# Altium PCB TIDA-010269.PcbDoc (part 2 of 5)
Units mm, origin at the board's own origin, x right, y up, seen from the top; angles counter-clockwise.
Board outline 87.61 x 53.51 mm, 8 copper layers (Top Layer, GND1, Signal 1, Power 1, Power 2, Signal 2, Layer 1, Bottom Layer), stack 1.645 mm thick; 482 components, 227 nets, 1562 pads, 953 vias.
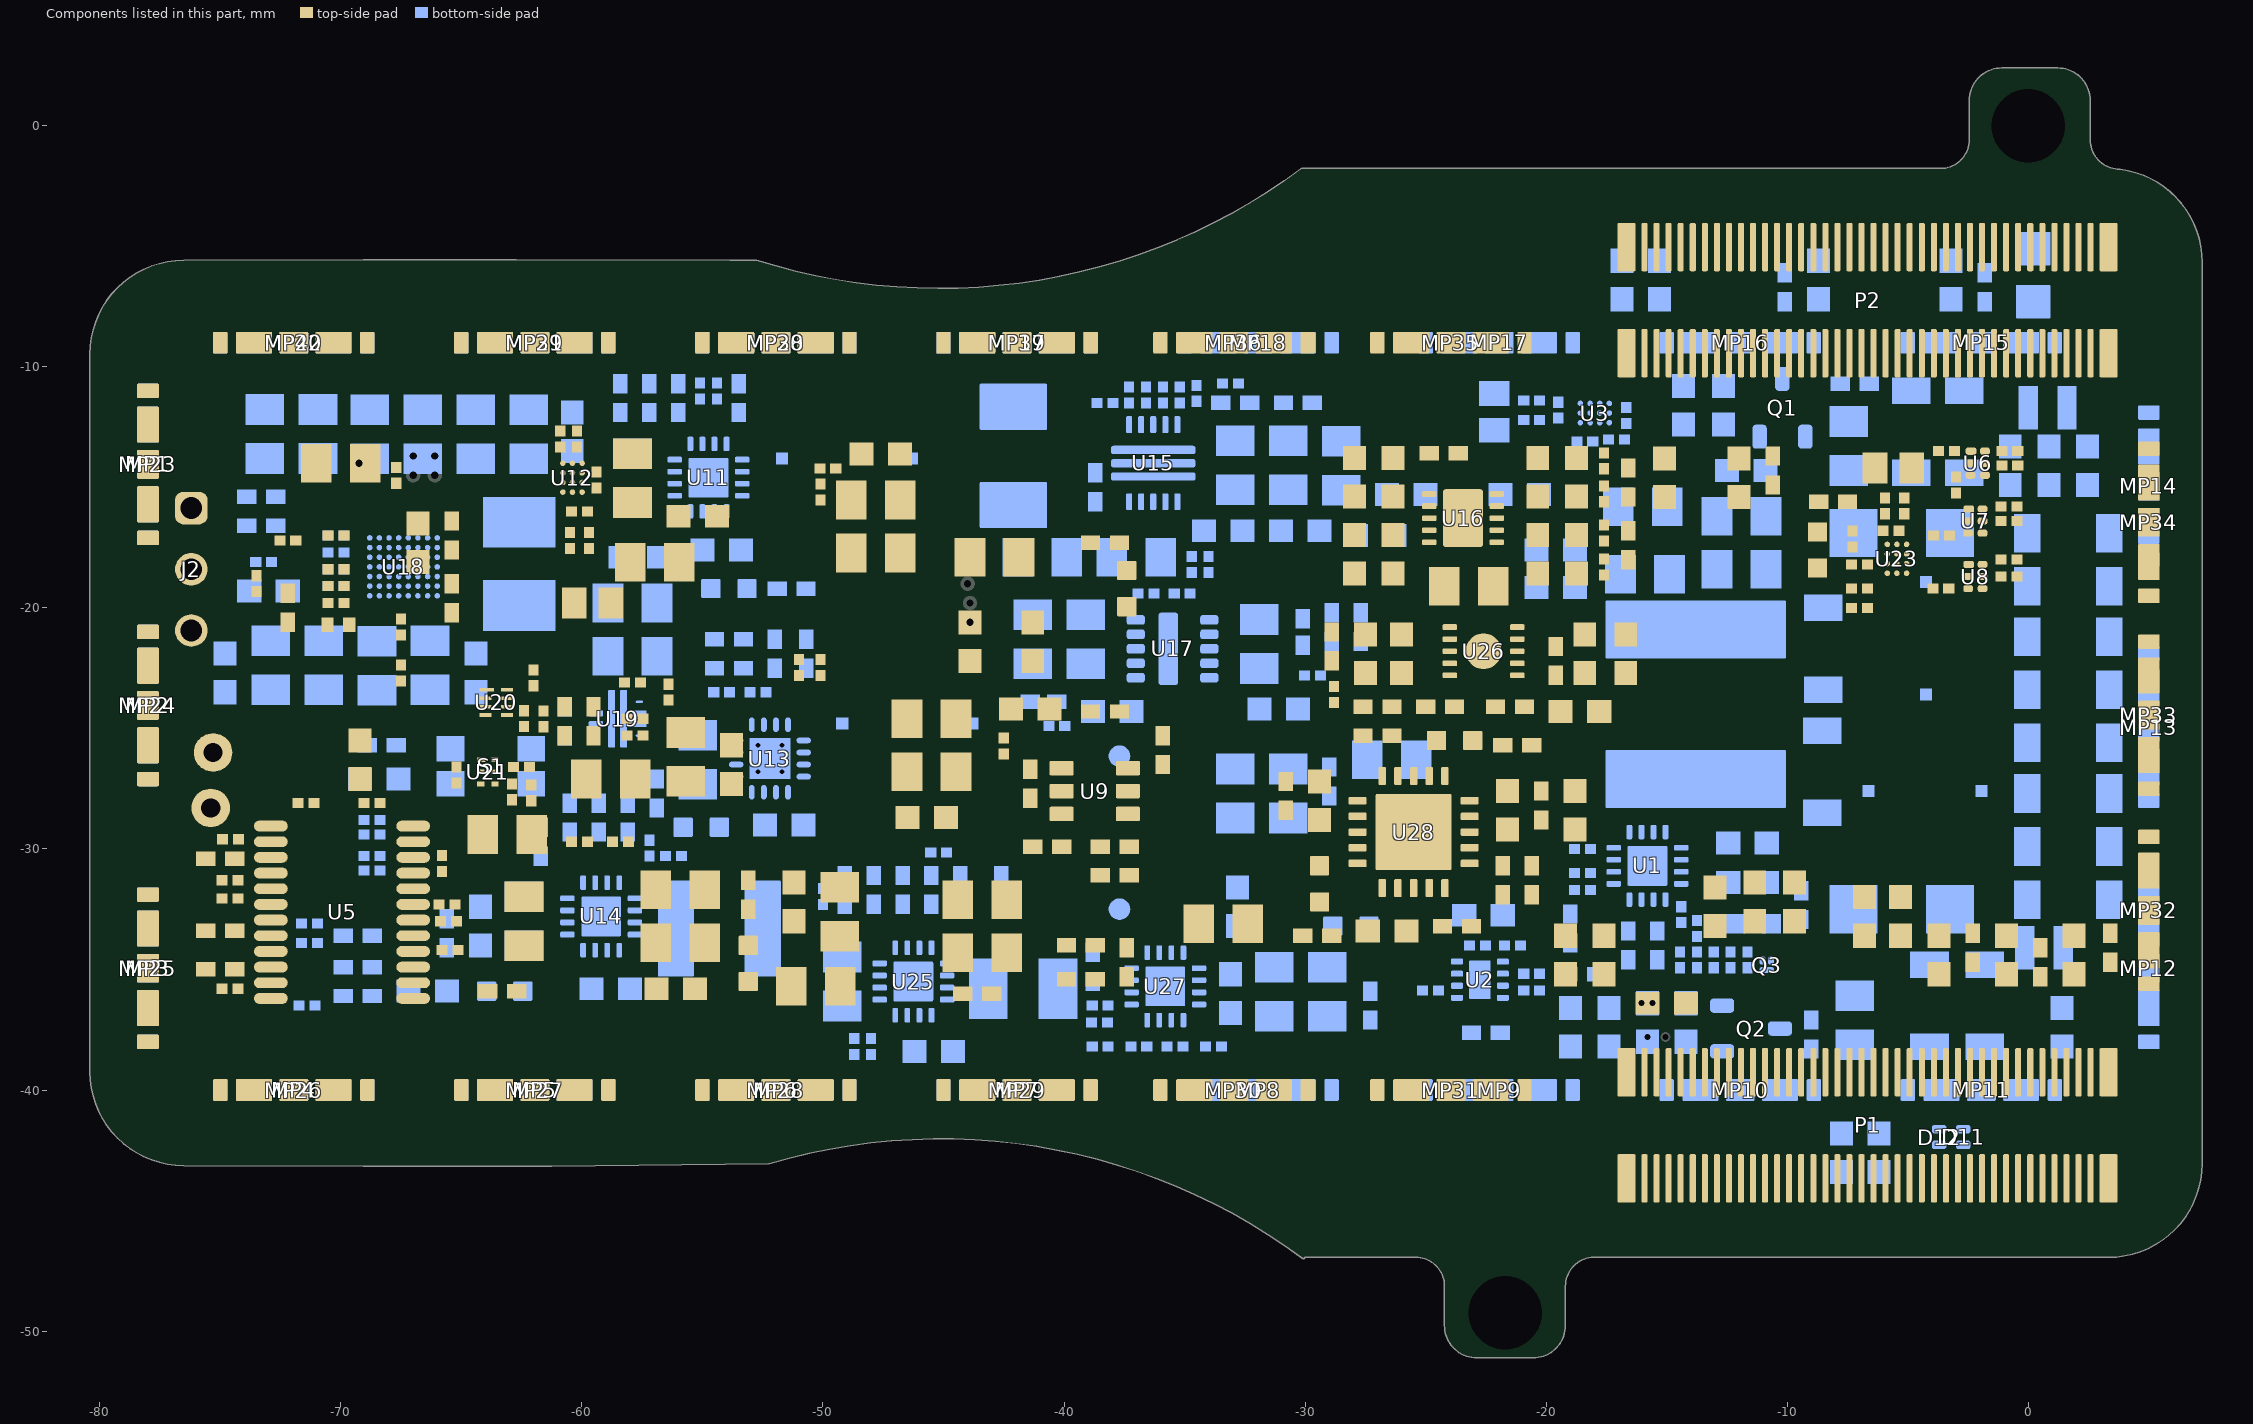
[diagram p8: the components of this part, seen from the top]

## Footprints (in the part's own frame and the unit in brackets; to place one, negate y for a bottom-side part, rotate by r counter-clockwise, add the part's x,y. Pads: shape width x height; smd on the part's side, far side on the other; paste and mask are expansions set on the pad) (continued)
DSG0008A-MFG [mm]
  rrect40% 0.5x0.25 smd paste+0 mask+0: 1(-0.95,0.75) 2(-0.95,0.25) 3(-0.95,-0.25) 4(-0.95,-0.75) 5(0.95,-0.75) 6(0.95,-0.25) 7(0.95,0.25) 8(0.95,0.75)
  rrect11% 0.9x1.6 smd paste-1000 mask+0: 9(0,0)
  silkscreen extent -1.88,-1.39 1,1.4, body extent -1,-1 1,1, height 0.8
FCC_disclaimer [mm]
FP-HCJ0805ZT0R00_0805-MFG [mm]
  rrect7% 1.4x1.44 smd paste+0 mask+0: 1(-1.1,0) 2(1.1,0)
  silkscreen extent 0,-0.72 0,0.72, body extent -1,-0.6 1,0.6, height 0.85
HSMx-C190_Amber [mm] "SMD, 2-Leads, Body 1.6x0.8mm"
  rect 0.8x0.8 smd: 1(-0.75,0) 2(0.75,0)
  silkscreen extent -1.2,-0.8 1.85,0.8, body extent -0.85,-0.45 0.85,0.45, height 0.9
HSMx-C191_Red [mm] "SMD, 2-Leads, Body 1.6x0.8mm"
  rrect12% 0.8x0.8 smd: 1(-0.75,0) 2(0.75,0)
  silkscreen extent -1.2,-0.8 1.85,0.8, body extent -0.85,-0.45 0.85,0.45, height 0.7
IHLP-2020CZ [mil] "Vishay Dale"
  rrect5% 75.5x110 smd: 1(-80.25,0) 2(80.25,0)
  silkscreen extent -101,-101 101,101, body extent -107,-101 107,101, height 113
LTST-C193_Green [mm] "SMD, 2-Leads, Body1.6x0.8mm"
  rect 0.8x0.8 smd: 1(-0.75,0) 2(0.75,0)
  silkscreen extent -1.2,-0.9 1.85,0.9, body extent -0.85,-0.45 0.85,0.45, height 0.45
Mill-Max_801-41-003-10-001000 [mm] "Receptacle, 2.54mm, 3x1, TH"
  rrect50% 1.35x1.35 hole 0.9: 1(-2.54,0)
  round 1.35 hole 0.9: 2(0,0) 3(2.54,0)
  silkscreen extent -3.81,-1.75 3.81,1.27, body extent -3.81,-1.27 3.81,1.27, height 7.01
NRS5030 [mm] "Taito Yuden"
  rrect7% 1.5x4 smd: 1(-1.8,0) 2(1.8,0)
  silkscreen extent -2.6,-2.6 2.6,2.6, body extent -2.55,-2.55 2.55,2.55, height 3.1
Panasonic_AXK5S80347Y [mm] "Receptacle, 0.5mm, 40x2, SMD"
  rrect13% 0.75x2 smd paste-2: 1(-10,2.2) 2(-10,-2.2) 79(10,2.2) 80(10,-2.2)
  rrect40% 0.25x2 smd paste-2: 3(-9.25,2.2) 4(-9.25,-2.2) 5(-8.75,2.2) 6(-8.75,-2.2) 7(-8.25,2.2) 8(-8.25,-2.2) 9(-7.75,2.2) 10(-7.75,-2.2) 11(-7.25,2.2) 12(-7.25,-2.2) 13(-6.75,2.2) 14(-6.75,-2.2) 15(-6.25,2.2) 16(-6.25,-2.2) 17(-5.75,2.2) 18(-5.75,-2.2) 19(-5.25,2.2) 20(-5.25,-2.2) 21(-4.75,2.2) 22(-4.75,-2.2) 23(-4.25,2.2) 24(-4.25,-2.2) 25(-3.75,2.2) 26(-3.75,-2.2) 27(-3.25,2.2) 28(-3.25,-2.2) 29(-2.75,2.2) 30(-2.75,-2.2) 31(-2.25,2.2) 32(-2.25,-2.2) 33(-1.75,2.2) 34(-1.75,-2.2) 35(-1.25,2.2) 36(-1.25,-2.2) 37(-0.75,2.2) 38(-0.75,-2.2) 39(-0.25,2.2) 40(-0.25,-2.2) 41(0.25,2.2) 42(0.25,-2.2) 43(0.75,2.2) 44(0.75,-2.2) 45(1.25,2.2) 46(1.25,-2.2) 47(1.75,2.2) 48(1.75,-2.2) 49(2.25,2.2) 50(2.25,-2.2) 51(2.75,2.2) 52(2.75,-2.2) 53(3.25,2.2) 54(3.25,-2.2) 55(3.75,2.2) 56(3.75,-2.2) 57(4.25,2.2) 58(4.25,-2.2) 59(4.75,2.2) 60(4.75,-2.2) 61(5.25,2.2) 62(5.25,-2.2) 63(5.75,2.2) 64(5.75,-2.2) 65(6.25,2.2) 66(6.25,-2.2) 67(6.75,2.2) 68(6.75,-2.2) 69(7.25,2.2) 70(7.25,-2.2) 71(7.75,2.2) 72(7.75,-2.2) 73(8.25,2.2) 74(8.25,-2.2) 75(8.75,2.2) 76(8.75,-2.2) 77(9.25,2.2) 78(9.25,-2.2)
  body extent -11.6,-2.7 11.6,2.7, height 6.05
PREYBG0056 [mm] "BGA, 56-Balls, Body 2.955x3.455mm, Pitch 0.4mm"
  round 0.23 smd paste-0.23: A1(-1.2,1.4) A2(-0.8,1.4) A3(-0.4,1.4) A4(0,1.4) A5(0.4,1.4) A6(0.8,1.4) A7(1.2,1.4) B1(-1.2,1) B2(-0.8,1) B3(-0.4,1) B4(0,1) B5(0.4,1) B6(0.8,1) B7(1.2,1) C1(-1.2,0.6) C2(-0.8,0.6) C3(-0.4,0.6) C4(0,0.6) C5(0.4,0.6) C6(0.8,0.6) C7(1.2,0.6) D1(-1.2,0.2) D2(-0.8,0.2) D3(-0.4,0.2) D4(0,0.2) D5(0.4,0.2) D6(0.8,0.2) D7(1.2,0.2) E1(-1.2,-0.2) E2(-0.8,-0.2) E3(-0.4,-0.2) E4(0,-0.2) E5(0.4,-0.2) E6(0.8,-0.2) E7(1.2,-0.2) F1(-1.2,-0.6) F2(-0.8,-0.6) F3(-0.4,-0.6) F4(0,-0.6) F5(0.4,-0.6) F6(0.8,-0.6) F7(1.2,-0.6) G1(-1.2,-1) G2(-0.8,-1) G3(-0.4,-1) G4(0,-1) G5(0.4,-1) G6(0.8,-1) G7(1.2,-1) H1(-1.2,-1.4) H2(-0.8,-1.4) H3(-0.4,-1.4) H4(0,-1.4) H5(0.4,-1.4) H6(0.8,-1.4) H7(1.2,-1.4)
  body extent -1.49,-1.74 1.49,1.74, height 0.5
PW0024A_N [mm] "TSOP, 24-Leads, Body 7.8x4.4mm, Pitch 0.65mm, IPC Medium Density"
  oval 1.4x0.45 smd: 1(-2.95,3.575) 2(-2.95,2.925) 3(-2.95,2.275) 4(-2.95,1.625) 5(-2.95,0.975) 6(-2.95,0.325) 7(-2.95,-0.325) 8(-2.95,-0.975) 9(-2.95,-1.625) 10(-2.95,-2.275) 11(-2.95,-2.925) 12(-2.95,-3.575) 13(2.95,-3.575) 14(2.95,-2.925) 15(2.95,-2.275) 16(2.95,-1.625) 17(2.95,-0.975) 18(2.95,-0.325) 19(2.95,0.325) 20(2.95,0.975) 21(2.95,1.625) 22(2.95,2.275) 23(2.95,2.925) 24(2.95,3.575)
  silkscreen extent -3.51,-3.95 1.6,4.04, body extent -3.21,-3.9 3.21,3.9, height 1
RGW0020A [mm] "VQFN-20"
  rrect32% 0.75x0.31 smd: 1(-2.325,1.3) 2(-2.325,0.65) 3(-2.325,0) 4(-2.325,-0.65) 5(-2.325,-1.3) 11(2.325,-1.3) 12(2.325,-0.65) 13(2.325,0) 14(2.325,0.65) 15(2.325,1.3)
  rrect32% 0.31x0.75 smd: 6(-1.3,-2.325) 7(-0.65,-2.325) 8(0,-2.325) 9(0.65,-2.325) 10(1.3,-2.325) 16(1.3,2.325) 17(0.65,2.325) 18(0,2.325) 19(-0.65,2.325) 20(-1.3,2.325)
  rrect3% 3.15x3.15 smd paste-1.575: 21(0,0)
  body extent -2.5,-2.5 2.5,2.5, height 1
RNW0013A [mm] "SMD, 13-Leads, Body 3x3.5mm, Pitch 0.5mm"
  rrect40% 0.7x0.25 smd: 1(-1.6,1) 2(-1.6,0.5) 3(-1.6,0) 4(-1.6,-0.5) 5(-1.6,-1) 9(1.6,-1) 10(1.6,-0.5) 11(1.6,0) 12(1.6,0.5) 13(1.6,1)
  rrect40% 0.25x1 on Bottom Paste: 6(-0.55,-1.2) 6(-0.55,0) 6(-0.55,1.2) 7(0,-1.2) 7(0,0) 7(0,1.2) 8(0.55,-1.2) 8(0.55,0) 8(0.55,1.2)
  rrect57% 0.35x3.5 smd paste-0.5 mask-0.05: 6(-0.55,0) 7(0,0) 8(0.55,0)
  silkscreen extent -1.9,-1.65 1.9,1.65, body extent -1.78,-1.53 1.78,1.53, height 1.01
RPW0010A [mm] "VQFN-HR-10"
  rrect100% 0.3x0.1 smd: 1(-0.9,0.7) 4(-0.9,-0.7) 7(0.9,-0.7) 10(0.9,0.7)
  rrect40% 0.6x0.25 smd: 2(-0.9,0.225) 3(-0.9,-0.225) 8(0.9,-0.225) 9(0.9,0.225)
  rrect33% 0.3x2.4 smd paste-0.25: 5(-0.25,0) 6(0.25,0)
  Top Layer region: -0.65,-0.55 -0.631,-0.554 -0.615,-0.565 -0.604,-0.581 -0.6,-0.6 -0.6,-0.6 -0.6,-1.15 -0.604,-1.169 -0.615,-1.185 -0.631,-1.196 -0.65,-1.2 -0.65,-1.2 -0.8,-1.2 -0.819,-1.196 -0.835,-1.185 -0.846,-1.169 -0.85,-1.15 -0.85,-1.15 -0.85,-0.85 -1.15,-0.85 -1.169,-0.846 -1.185,-0.835 -1.196,-0.819 -1.2,-0.8 -1.2,-0.8 -1.2,-0.6 -1.196,-0.581 -1.185,-0.565 -1.169,-0.554 -1.15,-0.55 -1.15,-0.55
  Top Layer region: -0.65,0.55 -0.631,0.554 -0.615,0.565 -0.604,0.581 -0.6,0.6 -0.6,0.6 -0.6,1.15 -0.604,1.169 -0.615,1.185 -0.631,1.196 -0.65,1.2 -0.65,1.2 -0.8,1.2 -0.819,1.196 -0.835,1.185 -0.846,1.169 -0.85,1.15 -0.85,1.15 -0.85,0.85 -1.15,0.85 -1.169,0.846 -1.185,0.835 -1.196,0.819 -1.2,0.8 -1.2,0.8 -1.2,0.6 -1.196,0.581 -1.185,0.565 -1.169,0.554 -1.15,0.55 -1.15,0.55
  Top Layer region: 0.65,0.55 0.631,0.554 0.615,0.565 0.604,0.581 0.6,0.6 0.6,0.6 0.6,1.15 0.604,1.169 0.615,1.185 0.631,1.196 0.65,1.2 0.65,1.2 0.8,1.2 0.819,1.196 0.835,1.185 0.846,1.169 0.85,1.15 0.85,1.15 0.85,0.85 1.15,0.85 1.169,0.846 1.185,0.835 1.196,0.819 1.2,0.8 1.2,0.8 1.2,0.6 1.196,0.581 1.185,0.565 1.169,0.554 1.15,0.55 1.15,0.55
  Top Layer region: 0.65,-0.55 0.631,-0.554 0.615,-0.565 0.604,-0.581 0.6,-0.6 0.6,-0.6 0.6,-1.15 0.604,-1.169 0.615,-1.185 0.631,-1.196 0.65,-1.2 0.65,-1.2 0.8,-1.2 0.819,-1.196 0.835,-1.185 0.846,-1.169 0.85,-1.15 0.85,-1.15 0.85,-0.85 1.15,-0.85 1.169,-0.846 1.185,-0.835 1.196,-0.819 1.2,-0.8 1.2,-0.8 1.2,-0.6 1.196,-0.581 1.185,-0.565 1.169,-0.554 1.15,-0.55 1.15,-0.55
  body extent -1,-1 1,1, height 1.01
RTE0016F#1 [mm] "Texas Insturments"
  rrect42% 0.6x0.24 smd: 1(-1.4,0.75) 2(-1.4,0.25) 3(-1.4,-0.25) 4(-1.4,-0.75) 9(1.4,-0.75) 10(1.4,-0.25) 11(1.4,0.25) 12(1.4,0.75)
  rrect42% 0.24x0.6 smd: 5(-0.75,-1.4) 6(-0.25,-1.4) 7(0.25,-1.4) 8(0.75,-1.4) 13(0.75,1.4) 14(0.25,1.4) 15(-0.25,1.4) 16(-0.75,1.4)
  rrect6% 1.65x1.65 smd paste-0.85: 17(0,0)
  rrect7% 1.51x1.51 on Bottom Paste: 17(0,0)
  silkscreen extent -1.73,-1.72 1.72,1.72, body extent -1.5,-1.5 1.5,1.5, height 0.8
RTE0016F#2 [mm] "Texas Insturments"
  oval 0.6x0.24 smd paste+0: 1(-1.4,0.75) 2(-1.4,0.25) 3(-1.4,-0.25) 4(-1.4,-0.75) 9(1.4,-0.75) 10(1.4,-0.25) 11(1.4,0.25) 12(1.4,0.75)
  oval 0.24x0.6 smd paste+0: 5(-0.75,-1.4) 6(-0.25,-1.4) 7(0.25,-1.4) 8(0.75,-1.4) 13(0.75,1.4) 14(0.25,1.4) 15(-0.25,1.4) 16(-0.75,1.4)
  rect 1.7x1.7 smd paste-1: 17(0,0)
  silkscreen extent -1.72,-1.73 1.72,1.73, body extent -1.58,-1.58 1.58,1.58, height 0.81
RTE0016K-MFG [mm]
  rrect42% 0.6x0.24 smd paste+0 mask+0: 1(-1.4,0.75) 2(-1.4,0.25) 3(-1.4,-0.25) 4(-1.4,-0.75) 9(1.4,-0.75) 10(1.4,-0.25) 11(1.4,0.25) 12(1.4,0.75)
  rrect42% 0.24x0.6 smd paste+0 mask+0: 5(-0.75,-1.4) 6(-0.25,-1.4) 7(0.25,-1.4) 8(0.75,-1.4) 13(0.75,1.4) 14(0.25,1.4) 15(-0.25,1.4) 16(-0.75,1.4)
  rrect6% 1.66x1.66 smd paste-1000 mask+0: 17(0,0)
  silkscreen extent -2.4,-1.58 1.58,1.57, body extent -1.5,-1.5 1.5,1.5, height 0.8
SIL0010A [mm] "MicoSiP, TI recommended land pattern"
  rrect50% 0.75x0.4 smd paste-0.05 mask-0.05: 1(-1.525,1.2) 2(-1.525,0.6) 3(-1.525,0) 4(-1.525,-0.6) 5(-1.525,-1.2) 6(1.525,-1.2) 7(1.525,-0.6) 8(1.525,0) 9(1.525,0.6) 10(1.525,1.2)
  rrect14% 0.7x0.833 on Bottom Paste: 11(-0.175,-1.03) 11(-0.175,0) 11(-0.175,1.03)
  rrect25% 0.8x3 smd paste-0.5 mask-0.05: 11(-0.175,0)
  silkscreen extent -1.9,-1.67 1.9,1.68, body extent -1.9,-1.5 1.9,1.5, height 1.49
SMA [mm] "Molded Diode, 2-Leads, Body 4.3x2.6mm, IPC Medium Density, based on OnSemi component dimensions and land pattern"
  rect 2x2 smd: 1(-2,0) 2(2,0)
  silkscreen extent -3.66,-1.57 2.79,1.58, body extent -2.6,-1.3 2.6,1.3, height 2.42
SML-P1_GREEN [mm] "ROHM"
  rect 0.5x0.6 smd: 1(-0.45,0) 2(0.45,0)
  silkscreen extent -0.95,-0.3 -0.95,0.3, body extent -0.53,-0.33 0.53,0.33, height 0.25
SOD-523 [mm] "NXP Semiconductor recommended land pattern, nominal STEP model"
  rect 0.8x0.6 smd paste-0.05: 1(-0.55,0) 2(0.55,0)
  silkscreen extent -1.65,-0.66 1.2,0.66, body extent -0.8,-0.4 0.8,0.4, height 0.72
SOT-23 [mm] "SOT23, 3-Leads, Body 2.9x1.3mm, Pitch 0.95mm, Lead Span 2.5mm, IPC Medium Density"
  rrect50% 1x0.6 smd: 1(-1.2,0.95) 2(-1.2,-0.95) 3(1.2,0)
  silkscreen extent -1.63,-1.5 0.7,1.5, body extent -1.16,-1.45 1.21,1.45, height 1
SW_434153017835 [mm] "SMD, 4-Leads, Body 3.5x2.9mm"
  rect 1.15x1.05 smd: 1(-1.675,0.725) 2(-1.675,-0.725) 3(1.675,0.725) 4(1.675,-0.725)
  silkscreen extent -0.7,-1.4 0.7,1.6, body extent -2.15,-1.45 2.15,1.45, height 1.7
TESTPOINT [mm]
  round 1.6 hole 0.8: 1(0,0)
TI_Stacked_Overlay_Small [mm]
  silkscreen extent -10.63,-2.49 10.63,2.49
VLCF4020 [mm] "TDK"
  rect 1.6x2.5 smd: 1(-1.45,0) 2(1.45,0)
  Top Layer region: 0.65,-1.95 1.55,-1.95 2.25,-1.25 2.25,-1.15 0.65,-1.15
  Top Layer region: 0.65,1.95 1.55,1.95 2.25,1.25 2.25,1.15 0.65,1.15
  Top Layer region: -0.65,1.95 -1.55,1.95 -2.25,1.25 -2.25,1.15 -0.65,1.15
  Top Layer region: -0.65,-1.95 -1.55,-1.95 -2.25,-1.25 -2.25,-1.15 -0.65,-1.15
  silkscreen extent -0.4,-2.1 0.4,2.1, body extent -2.05,-2.05 2.05,2.05, height 2
VLCF5020 [mm] "TDK"
  rect 2.1x3 smd: 1(-1.725,0) 2(1.725,0)
  Top Layer region: -0.675,2.45 -1.875,2.45 -2.775,1.55 -2.775,1.4 -0.675,1.4
  Top Layer region: -0.675,-2.45 -1.875,-2.45 -2.775,-1.55 -2.775,-1.4 -0.675,-1.4
  Top Layer region: 0.675,-2.45 1.875,-2.45 2.775,-1.55 2.775,-1.4 0.675,-1.4
  Top Layer region: 0.675,2.4 1.875,2.4 2.775,1.5 2.775,1.35 0.675,1.35
  body extent -2.6,-2.6 2.6,2.6, height 2
WE-LQS_8040 [mm] "SMD, 2-Leads, Body 8x8mm"
  rrect4% 2.4x7.5 smd: 1(-3.1,0) 2(3.1,0)
  body extent -4,-4 4,4, height 4.2
WE-PMI_0806HS [mm] "WURTH"
  rect 0.8x1.8 smd: 1(-0.8,0) 2(0.8,0)
  body extent -1.1,-0.9 1.1,0.9, height 1
WE-TPC-LH [mm] "Wurth Elektronik recommended land pattern, 2009-01-15"
  rect 0.5x0.5 smd: 1(-2.7,0) 2(2.7,0)
  Top Layer region: -0.95,3.15 -0.95,3.15 -0.95,1.987 -1.228,1.838 -1.563,1.563 -1.838,1.228 -2.042,0.846 -2.168,0.431 -2.211,0 -2.168,-0.431 -2.042,-0.846 -1.838,-1.228 -1.563,-1.563 -1.228,-1.838 -0.95,-1.987 -0.95,-3.15 -3.15,-3.15 -3.15,-3.15 -3.15,3.15 -0.95,3.15
  Top Layer region: 0.95,3.15 0.95,3.15 0.95,1.987 1.228,1.838 1.563,1.563 1.838,1.228 2.042,0.846 2.168,0.431 2.211,0 2.168,-0.431 2.042,-0.846 1.838,-1.228 1.563,-1.563 1.228,-1.838 0.95,-1.987 0.95,-3.15 3.15,-3.15 3.15,-3.15 3.15,3.15 0.95,3.15
  silkscreen extent -3.4,-3.4 3.4,3.4, body extent -3.05,-3.05 3.05,3.05, height 3
WE-TPC_4828 [mm] "Wurth Elektronik recommended land pattern"
  rect 0.5x0.5 smd: 1(-2.35,0) 2(2.325,0)
  Top Layer region: 0.75,1.64 1.005,1.504 1.279,1.279 1.504,1.005 1.671,0.692 1.774,0.353 1.809,0 1.774,-0.353 1.671,-0.692 1.504,-1.005 1.279,-1.279 1.005,-1.504 0.75,-1.64 0.75,-2.65 2.75,-2.65 2.75,2.65 0.75,2.65
  Top Layer region: -0.75,1.64 -1.005,1.504 -1.279,1.279 -1.504,1.005 -1.671,0.692 -1.774,0.353 -1.809,0 -1.774,-0.353 -1.671,-0.692 -1.504,-1.005 -1.279,-1.279 -1.005,-1.504 -0.75,-1.64 -0.75,-2.65 -2.75,-2.65 -2.75,2.65 -0.75,2.65
  silkscreen extent -0.5,-2.6 0.5,2.63, body extent -2.5,-2.5 2.5,2.5, height 2
WE-TPC_6823 [mm] "Wurth"
  round 0.9 smd: 1(0,3.2) 2(0,-3.15)
  Top Layer region: 3.65,-1.05 2.5,-1.05 2.485,-1.055 1.743,-2.062 0.626,-2.626 -0.626,-2.626 -1.743,-2.062 -2.485,-1.055 -2.485,-1.055 -2.5,-1.05 -3.65,-1.05 -3.65,-3.65 3.65,-3.65
  Top Layer region: -3.65,1.05 -2.5,1.05 -2.485,1.055 -1.743,2.062 -0.626,2.626 0.626,2.626 1.743,2.062 2.485,1.055 2.485,1.055 2.5,1.05 3.65,1.05 3.65,3.65 -3.65,3.65
  silkscreen extent -3.6,-0.8 3.6,0.8, body extent -3.5,-3.5 3.5,3.5, height 2.5
WEEE_Minimum [mm] "WEEElie bin"
  silkscreen extent -2.42,-4.38 2.52,2.65
WSLP0805 [mm] "Vishay"
  rect 1.02x1.27 smd: 1(-0.76,0) 2(0.76,0)
  silkscreen extent -0.6,-0.9 0.6,0.9, body extent -1.14,-0.76 1.14,0.76, height 0.64
YFF0012AKAD [mm] "TI DSBGA 1.675x1.418mm"
  round 0.23 smd paste-0.13 mask+0.038: A1(-0.4,0.6) A2(0,0.6) A3(0.4,0.6) B1(-0.4,0.2) B2(0,0.2) B3(0.4,0.2) C1(-0.4,-0.2) C2(0,-0.2) C3(0.4,-0.2) D1(-0.4,-0.6) D2(0,-0.6) D3(0.4,-0.6)
  silkscreen extent -0.8,-0.93 0.8,0.92, body extent -0.71,-0.84 0.71,0.84, height 0.63
YJM0003A [mm] "SMT, 3-Leads, Body 0.69x0.6mm"
  rrect80% 0.35x0.25 smd paste-0.2 mask-0.05: 1(-0.175,0.175) 2(-0.175,-0.175)
  rrect50% 0.25x0.2 on Bottom Paste: 1(-0.175,0.2) 2(-0.175,-0.2)
  rrect80% 0.25x0.6 smd paste-0.05 mask-0.05: 3(0.225,0)
  body extent -0.35,-0.3 0.35,0.3, height 0.35

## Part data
C1 C6 C7 C8 C9 C10 C11 C15 C18 C19 C20 C21 C22 C23: library part CMP-0008724-2, "CAP, CERM, 2.2 uF, 100 V, +/- 10%, X7S, 1206", Cap_Case=1206_180, Manufacturer=TDK, Supplier Part Number 1=445-5207-1-ND, TempCo=X7S, Tolerance_%=10%, Value1="0.005718 ohm", Value2=100V, ValueDisplayed=2.2uF
C2: library part CMP-0007891-2, "CAP, CERM, 1 uF, 100 V, +/- 10%, X7S, 0805", Cap_Case=0805, Manufacturer=TDK, Supplier Part Number 1=445-5205-1-ND, TempCo=X7S, Tolerance_%=10%, Value1="0.008255 ohm", Value2=100V, ValueDisplayed=1uF
C3 C4 C58 C59 C63 C64 C72 C74 C75 C76 C79 C81 C82 C84 C95 C96 C99 C100 C101 C123 C131 C132 C139 C140 C141 C174 C175 C177 C178 C192 C193 C195 C196: library part CMP-0078699-1, "CAP, CERM, 47 µF, 10 V,+/- 20%, X5R, 0805", Cap_Case=0805, Manufacturer=MuRata, Supplier Part Number 1=490-9961-1-ND, TempCo=X5R, Tolerance_%=20%, Value2=10V, ValueDisplayed=47µF
C5 C25 C56 C57 C60 C65 C70 C71 C73 C77 C83 C85 C107 C109 C114 C117 C122 C125 C130 C133 C143 C150 C154 C155 C171 C176 C183 C189 C194: library part CMP-0006837-2, "CAP, CERM, 0.1 uF, 50 V, +/- 10%, X7R, 0603", Cap_Case=0603, Manufacturer="Wurth Elektronik", TempCo=X7R, Tolerance_%=10%, Value1=Unknown, Value2=50V, ValueDisplayed=0.1uF
C12: library part CMP-0007297-3, "CAP, CERM, 4.7 uF, 25 V, +/- 10%, X6S, 0603", Cap_Case=0603, Manufacturer=MuRata, Supplier Part Number 1=490-7199-1-ND, TempCo=X6S, Tolerance_%=10%, Value1=Unknown, Value2=25V, ValueDisplayed=4.7uF
C13 C17: library part CMP-0007470-5, "CAP, CERM, 0.1 uF, 100 V, +/- 10%, X7R, 0603", Cap_Case=0603, Manufacturer=MuRata, Supplier Part Number 1=490-6439-1-ND, TempCo=X7R, Tolerance_%=10%, Value1=Unknown, Value2=100V, ValueDisplayed=0.1uF
C14: library part CMP-0079154-1, "CAP, CERM, 1 µF, 16 V,+/- 10%, X7R, AEC-Q200 Grade 1, 0603", Cap_Case=0603, Manufacturer=MuRata, Supplier Part Number 1=490-12657-1-ND, TempCo=X7R, Tolerance_%=10%, Value2=16V, ValueDisplayed=1µF
C16 C24 C29 C39 C40 C43 C51 C52 C68 C91 C92 C94 C108 C137 C152 C153 C179 C180 C187 C191 C197 C200 C202 C205 C207: library part CMP-0006607-1, "CAP, CERM, 0.1 uF, 25 V, +/- 10%, X5R, 0402", Cap_Case=0402, Manufacturer=MuRata, Supplier Part Number 1=490-5920-1-ND, TempCo=X5R, Tolerance_%=10%, Value1=Unknown, Value2=25V, ValueDisplayed=0.1uF
C26 C27 C32 C34 C35 C53 C54 C55 C61 C66 C135 C138 C148 C151 C157: library part CMP-0009637-1, "CAP, CERM, 0.1 uF, 16 V, +/- 10%, X6S, 0201", Cap_Case=0201, Manufacturer=TDK, Supplier Part Number 1=445-15903-1-ND, TempCo=X6S, Tolerance_%=10%, Value1=Unknown, Value2=16V, ValueDisplayed=0.1uF
C28: library part CMP-0006663-2, "CAP, CERM, 2200 pF, 25 V, +/- 10%, X7R, 0402", Cap_Case=0402, Manufacturer=MuRata, Supplier Part Number 1=490-5419-1-ND, TempCo=X7R, Tolerance_%=10%, Value1=Unknown, Value2=25V, ValueDisplayed=2200pF
C30 C104: library part CMP-0009762-1, "CAP, CERM, 100 pF, 25 V, +/- 5%, C0G/NP0, 0201", Cap_Case=0201, Manufacturer=MuRata, Supplier Part Number 1=81-GRM033R71E101JA1D, TempCo=C0G/NP0, Tolerance_%=5%, Value1=Unknown, Value2=25V, ValueDisplayed=100pF
C31: library part CMP-0007891-1, "CAP, CERM, 1 uF, 100 V, +/- 10%, X7S, 0805", Cap_Case=0805, Manufacturer=TDK, Supplier Part Number 1=445-5205-1-ND, TempCo=X7S, Tolerance_%=10%, Value1="0.008255 ohm", Value2=100V, ValueDisplayed=1uF
C33: library part CMP-0006563-2, "CAP, CERM, 1 uF, 10 V, +/- 10%, X5R, 0402", Cap_Case=0402, Manufacturer=MuRata, Supplier Part Number 1=490-3890-1-ND, TempCo=X5R, Tolerance_%=10%, Value1=Unknown, Value2=10V, ValueDisplayed=1uF
C41 C42: library part CMP-0006607-2, "CAP, CERM, 0.1 uF, 25 V, +/- 10%, X5R, 0402", Cap_Case=0402, Manufacturer=MuRata, Supplier Part Number 1=490-5920-1-ND, TempCo=X5R, Tolerance_%=10%, Value1=Unknown, Value2=25V, ValueDisplayed=0.1uF
C47 C97 C169 C184: library part CMP-0007329-4, "CAP, CERM, 4.7 uF, 10 V, +/- 20%, X5R, 0603", Cap_Case=0603, Manufacturer=MuRata, TempCo=X5R, Tolerance_%=20%, Value1=Unknown, Value2=10V, ValueDisplayed=4.7uF
C50: library part CMP-0006286-1, "CAP, CERM, 1 uF, 16 V, +/- 10%, X6S, 0402", Cap_Case=0402, Manufacturer=TDK, Supplier Part Number 1=445-9086-1-ND, TempCo=X6S, Tolerance_%=10%, Value1="0.011416 ohm", Value2=16V, ValueDisplayed=1uF
C62 C67 C78 C80 C88 C90 C182 C186 C198: library part CMP-0006686-1, "CAP, CERM, 2700 pF, 50 V, +/- 10%, X7R, 0402", Cap_Case=0402, Manufacturer=MuRata, Supplier Part Number 1=490-1306-1-ND, TempCo=X7R, Tolerance_%=10%, Value1=Unknown, Value2=50V, ValueDisplayed=2700pF
C86 C87 C204: library part CMP-0006837-2, "CAP, CERM, 0.1 uF, 50 V, +/- 10%, X7R, 0603", Cap_Case=0603, Manufacturer="Wurth Elektronik", PartNumber=885012206095, TempCo=X7R, Tolerance_%=10%, Value1=Unknown, Value2=50V, ValueDisplayed=0.1uF
C98 C102 C103 C110 C113 C115 C116: library part CMP-0007336-4, "CAP, CERM, 10 uF, 16 V, +/- 20%, X5R, 0603", Cap_Case=0603, Manufacturer=MuRata, Supplier Part Number 1=GRM188R61C106MAALD-ND, TempCo=X5R, Tolerance_%=20%, Value1=Unknown, Value2=16V, ValueDisplayed=10uF
C106: library part CMP-0064916-2, "CAP, CERM, 10 pF, 50 V,+/- 1%, C0G/NP0, 0402", Cap_Case=0402, Manufacturer=MuRata, Supplier Part Number 1=490-6186-1-ND, TempCo=C0G/NP0, Tolerance_%=1%, Value1=Unknown, Value2=50V, ValueDisplayed=10pF
C111 C112 C118: library part CMP-0006227-2, "CAP, CERM, 0.01 uF, 16 V, +/- 10%, X7R, 0402", Cap_Case=0402, Manufacturer="Wurth Elektronik", Supplier Part Number 1=710-885012205031, TempCo=X7R, Tolerance_%=10%, Value1=Unknown, Value2=16V, ValueDisplayed=0.01uF
C119: library part CMP-0006217-1, "CAP, CERM, 100 pF, 50 V, +/- 5%, C0G/NP0, 0402", Cap_Case=0402, Manufacturer="Wurth Elektronik", Supplier Part Number 1=732-7475-1-ND, TempCo=C0G/NP0, Tolerance_%=5%, Value1=Unknown, Value2=50V, ValueDisplayed=100pF
C120 C121: library part CMP-0007691-1, "CAP, CERM, 10 uF, 10 V, +/- 10%, X7R, 0805", Cap_Case=0805, Manufacturer="Wurth Elektronik", Supplier Part Number 1=710-885012207026, TempCo=X7R, Tolerance_%=10%, Value1=Unknown, Value2=10V, ValueDisplayed=10uF
C124: library part CMP-0006830-3, "CAP, CERM, 0.22 uF, 16 V, +/- 10%, X7R, 0603", Cap_Case=0603, Manufacturer="Wurth Elektronik", Supplier Part Number 1=710-885012206048, TempCo=X7R, Tolerance_%=10%, Value1=Unknown, Value2=16V, ValueDisplayed=0.22uF
C126 C127 C128 C129 C142 C145 C146: library part CMP-0008268-1, "CAP, CERM, 10 uF, 10 V, +/- 10%, X6S, 0805", Cap_Case=0805, Manufacturer=MuRata, Supplier Part Number 1=GRM21BC81A106KE18L-ND, TempCo=X6S, Tolerance_%=10%, Value1=Unknown, Value2=10V, ValueDisplayed=10uF
C134 C147: library part CMP-0006669-2, "CAP, CERM, 0.047 uF, 25 V, +/- 10%, X7R, 0402", Cap_Case=0402, Manufacturer=MuRata, Supplier Part Number 1=490-3254-1-ND, TempCo=X7R, Tolerance_%=10%, Value1=Unknown, Value2=25V, ValueDisplayed=0.047uF
C136: library part CMP-0006671-2, "CAP, CERM, 6800 pF, 25 V, +/- 10%, X7R, 0402", Cap_Case=0402, Manufacturer=MuRata, Supplier Part Number 1=490-1310-1-ND, TempCo=X7R, Tolerance_%=10%, Value1=Unknown, Value2=25V, ValueDisplayed=6800pF
C144: library part CMP-0081052-1, "CAP, CERM, 4.7 µF, 16 V,+/- 10%, X5R, AEC-Q200 Grade 3, 0603", Cap_Case=0603, Manufacturer=MuRata, Supplier Part Number 1=490-12319-1-ND, TempCo=X5R, Tolerance_%=10%, Value2=16V, ValueDisplayed=4.7µF
C149: library part CMP-0080092-1, "CAP, CERM, 1000 pF, 25 V,+/- 1%, C0G/NP0, 0603", Cap_Case=0603, Manufacturer=Kemet, Supplier Part Number 1=399-7825-1-ND, TempCo=C0G/NP0, Tolerance_%=1%, Value2=25V, ValueDisplayed=1000pF
C172: library part CMP-0006831-1, "CAP, CERM, 1 uF, 16 V, +/- 10%, X7R, 0603", Cap_Case=0603, Manufacturer="Wurth Elektronik", Supplier Part Number 1=710-885012206052, TempCo=X7R, Tolerance_%=10%, Value1=Unknown, Value2=16V, ValueDisplayed=1uF
C173 C181 C190 C199 C203: library part CMP-0007003-5, "CAP, CERM, 10 uF, 10 V, +/- 20%, X5R, 0603", Cap_Case=0603, Manufacturer=TDK, Supplier Part Number 1=445-6853-1-ND, TempCo=X5R, Tolerance_%=20%, Value1="0.0078 ohm", Value2=10V, ValueDisplayed=10uF
C185: library part CMP-0006389-2, "CAP, CERM, 470 pF, 25 V, +/- 5%, C0G/NP0, 0402", Cap_Case=0402, Manufacturer=MuRata, Supplier Part Number 1=GRM1555C1E471JA01D-ND, TempCo=C0G/NP0, Tolerance_%=5%, Value1=Unknown, Value2=25V, ValueDisplayed=470pF
C201: library part CMP-0006831-4, "CAP, CERM, 1 uF, 16 V, +/- 10%, X7R, 0603", Cap_Case=0603, Manufacturer="Wurth Elektronik", Supplier Part Number 1=710-885012206052, TempCo=X7R, Tolerance_%=10%, Value1=Unknown, Value2=16V, ValueDisplayed=1uF
C206: library part CMP-0006680-2, "CAP, CERM, 1800 pF, 50 V, +/- 10%, X7R, 0402", Cap_Case=0402, Manufacturer=MuRata, Supplier Part Number 1=490-3246-1-ND, TempCo=X7R, Tolerance_%=10%, Value1=Unknown, Value2=50V, ValueDisplayed=1800pF
D1 D2: library part CMP-0028752-1, "Diode, Schottky, 150 V, 1 A, SMA", Manufacturer=STMicroelectronics, Supplier Part Number 1=497-7545-1-ND, Value1=1A, Value2=0.78V
D3: library part CMP-0079921-3, "LED, Green, SMD", Color=Green, Manufacturer=Lite-On, Value1=W, Value2=2V
D4 D5 D6 D7 D14 D15 D16 D17: library part CMP-0078541-2, "LED, Red, SMD", Color=Red, Manufacturer=Avago, Value1=W, Value2=1.9V
D8 D9: library part CMP-0076957-2, "Diode, Switching, 75 V, 0.3 A, SOD-523", Manufacturer="Micro Commercial Components", Supplier Part Number 1=1N4148XTPMSCT-ND, Value1=0.3A, Value2=1.25V
D10: library part CMP-0003041-3, "LED, Amber, SMD", Color=Amber, Manufacturer=Avago, Power_TotalModule=60mW, Value1=0.06W, Value2=1.9V
D11 D12: library part CMP-0084110-3, "1-Channel 30 kV ESD Protection Diode With Low Clamping Voltage in 0402 Package, DPY0002A (X1SON-2)", Alternate Manufacturer="Texas Instruments", Operating Temperature Range="-40 to 125 C", Rating=Catalog
D13: library part CMP-0002873-3, "LED, Green, SMD", Color=green, Manufacturer=Rohm, Value1=W, Value2=2.2V
J2: library part CMP-0076709-1, "Receptacle, 2.54mm, 3x1, Gold, TH", Color=Black, Manufacturer=Mill-Max, Supplier Part Number 1=575-8014100310001000
L1: library part CMP-0086317-1, "Inductor, Shielded, Ferrite, 100 µH, 1.2 A, 0.377 ohm, SMD", Manufacturer="Wurth Elektronik", Value1="0.377 ohm", Value2=1.2A, ValueDisplayed=100µH
L2 L7: library part CMP-0064322-1, "Inductor, Shielded Drum Core, Metal Composite, 3.3 uH, 0.26 A, 0.13 ohm, SMD", Manufacturer="Wurth Elektronik", Supplier Part Number 1=732-2955-1-ND, Value1="0.13 ohm", Value2=0.26A, ValueDisplayed=3.3uH
L3 L5: library part CMP-0064699-2, "Inductor, Shielded Drum Core, Metal Composite, 1mH, 0.08 A, 5.4 ohm, SMD", Manufacturer="Wurth Elektronik", Supplier Part Number 1=732-3662-1-ND, Value1="5.4 ohm", Value2=0.08A, ValueDisplayed=1mH
L4 L6 L17 L18: library part CMP-0003346-2, "Ferrite Bead, 2500 ohm @ 100 MHz, 0.15 A, 0603", Manufacturer=MuRata, Supplier Part Number 1=490-1028-1-ND, Value1="1.5 ohm", Value2=0.15A, ValueDisplayed="2500 ohm"
L8: library part CMP-0003349-2, "Ferrite Bead, 1500 ohm @ 100 MHz, 0.5 A, 0603", Manufacturer=MuRata, Supplier Part Number 1=490-5216-1-ND, Value1="0.5 ohm", Value2=0.5A, ValueDisplayed="1500 ohm"
L9: library part CMP-0003349-1, "Ferrite Bead, 1500 ohm @ 100 MHz, 0.5 A, 0603", Manufacturer=MuRata, Supplier Part Number 1=490-5216-1-ND, Value1="0.5 ohm", Value2=0.5A, ValueDisplayed="1500 ohm"
L10 L12: library part CMP-0064424-1, "Inductor, Shielded Drum Core, Ferrite, 33 uH, 0.75 A, 0.155 ohm, SMD", Manufacturer="Wurth Elektronik", Supplier Part Number 1=732-1049-1-ND, Value1="0.155 ohm", Value2=0.75A, ValueDisplayed=33uH
L11 L13 L25 L27: library part CMP-0003353-1, "Ferrite Bead, 220 ohm @ 100 MHz, 2.5 A, 0603", Manufacturer=MuRata, Supplier Part Number 1=490-5225-1-ND, Value1="0.04 ohm", Value2=2.5A, ValueDisplayed="220 ohm"
L14: library part CMP-0081757-1, "Inductor, Shielded, Ferrite, 6.8 µH, 2.3 A, 0.0676 ohm, AEC-Q200 Grade 1, SMD", Manufacturer="Taiyo Yuden", Value1="0.0676 ohm", Value2=2.3A, ValueDisplayed=6.8µH
L15: library part CMP-0003352-2, "Ferrite Bead, 120 ohm @ 100 MHz, 3 A, 0603", Manufacturer=MuRata, Supplier Part Number 1=490-3996-1-ND, Value1="0.025 ohm", Value2=3A, ValueDisplayed="120 ohm"
L16: library part CMP-0063603-4, "Inductor, Shielded Drum Core, Powdered Iron, 15 uH, 1.9 A, 0.265 ohm, SMD", Manufacturer=Vishay-Dale, Supplier Part Number 1=541-1273-1-ND, Value1="0.265 ohm", Value2=1.9A, ValueDisplayed=15uH
L19: library part CMP-0062911-1, "Inductor, Shielded, Ferrite, 2.2 uH, 2.62 A, 0.043 ohm, SMD", Manufacturer=TDK, Supplier Part Number 1=445-4557-1-ND, Value1="0.043 ohm", Value2=2.62A, ValueDisplayed=2.2uH
L20 L21 L22: "Ferrite Bead, 30 ohm @ 100 MHz, 3 A, 0603", Manufacturer="Wurth Elektronik", Supplier Part Number 1=732-1591-1-ND, Value1="0.04 ohm", Value2=3A, ValueDisplayed="30 ohm"
L23: library part CMP-0062895-1, "Inductor, Shielded, Ferrite, 2.2 uH, 1.72 A, 0.059 ohm, SMD", Manufacturer=TDK, Supplier Part Number 1=445-3182-1-ND, Value1="0.059 ohm", Value2=1.72A, ValueDisplayed=2.2uH
L24 L28 L29: library part CMP-0003180-2, "Ferrite Bead, 30 ohm @ 100 MHz, 3 A, 0603", Manufacturer="Wurth Elektronik", Supplier Part Number 1=732-1591-1-ND, Value1="0.04 ohm", Value2=3A, ValueDisplayed="30 ohm"
L26: library part CMP-0063839-1, "Inductor, Shielded Drum Core, Metal Composite, 2.2 uH, 2.7 A, 0.017 ohm, SMD", Manufacturer="Wurth Elektronik", Supplier Part Number 1=732-3671-1-ND, Value1="0.017 ohm", Value2=2.7A, ValueDisplayed=2.2uH
Logo2: library part IEC_HighVoltage, "IEC 61010-1 High Voltage Warning"
Logo3: library part Pb-Free
Logo5: library part CMP-0074769-3, Manufacturer="Texas Instruments"
MP1 MP2 MP3 MP4 MP5 MP6 MP7 MP8 MP9 MP10 MP11 MP12 MP13 MP14 MP15 MP16 MP17 MP18 MP19 MP20 MP21 MP22 MP23 MP24 MP25 MP26 MP27 MP28 MP29 MP30 MP31 MP32 MP33 MP34 MP35 MP36 MP37 MP38 MP39 MP40: library part CMP-0037144-1, "SHIELD (T0.3) CAN CLIP L6.50*W0.8*H1.28mm", Manufacturer="Texas Instruments", Operating Temperature Range=to
P1 P2: library part CMP-0084862-1, "Receptacle, 0.5mm, 40x2, Gold, SMD", Color=White, Manufacturer=Panasonic
Q1: library part CMP-0074710-1, "Transistor, NPN, 150 V, 1 A, AEC-Q101, SOT-23", Manufacturer="Diodes Inc.", Supplier Part Number 1=FMMT495CT-ND, Value1="1 A", Value2=300.0
Q2: library part CMP-0000370-2, "Transistor, PNP, 200 V, 0.3 A, SOT-23", Manufacturer="Diodes Inc.", Supplier Part Number 1=FMMT596CT-ND, Value1="0.3 A", Value2=300
Q3: library part CMP-0000206-2, "MOSFET, N-CH, 20 V, 0.5 A, YJM0003A (PICOSTAR-3)", Alternate Manufacturer=None, Manufacturer="Texas Instruments", Supplier Part Number 1=296-44373-1-ND, Value1=1.4, Value2="0.216 nC"
R1 R23: library part CMP-0026748-1, "RES, 10.0 k, 1%, 0.063 W, AEC-Q200 Grade 0, 0402", Manufacturer="KOA Speer", Power_W=63mW, Supplier Part Number 1=660-RK73H1ETTP1002F, TempCo="100 ppm/C", Tolerance_%=1%, Value2=0.063W, Value_Code=10k0, ValueDisplayed=10.0k
R2 R3 R67 R81 R82 R91 R117 R153 R154 R163 R175: library part CMP-0020803-2, "RES, 0, 5%, 0.125 W, 0805", Manufacturer="Yageo America", Power_W=125mW, Supplier Part Number 1=311-0.0ARCT-ND, TempCo="200 ppm/C", Tolerance_%=5%, Value2=0.125W, Value_Code=0000, ValueDisplayed=0
R4: library part CMP-0023238-5, "RES, 68.1 k, 1%, 0.1 W, 0603", Manufacturer=Yageo, Power_W=100mW, Supplier Part Number 1=311-68.1KHRCT-ND, TempCo="100 ppm/C", Tolerance_%=1%, Value2=0.1W, Value_Code=68k1, ValueDisplayed=68.1k
R5: library part CMP-0027766-1, "RES, 53.6 k, 1%, 0.05 W, 0201", Manufacturer="Yageo America", Power_W=50mW, Supplier Part Number 1=YAG2722CT-ND, TempCo="200 ppm/C", Tolerance_%=1%, Value2=0.05W, Value_Code=53k6, ValueDisplayed=53.6k
R6 R14: library part CMP-0082530-1, "RES, 100 k, 1%, 0.1 W, 0603", Manufacturer=Panasonic, PartNumber=ERJ-3EKF1003V, Power_W=100mW, Supplier Part Number 1=P100KHCT-ND, TempCo="200 ppm/C", Tolerance_%=1%, Value1=5%, Value2=0.1W, Value_Code=100k
R7: library part CMP-0023195-5, "RES, 59.0 k, 1%, 0.1 W, 0603", Manufacturer=Yageo, Power_W=100mW, Supplier Part Number 1=311-59.0KHRCT-ND, TempCo="100 ppm/C", Tolerance_%=1%, Value2=0.1W, Value_Code=59k0, ValueDisplayed=59.0k
R8 R21: library part CMP-0027973-1, "RES, 1.00 k, 1%, 0.05 W, 0201", Manufacturer="Yageo America", Power_W=50mW, Supplier Part Number 1=603-RC0201FR-7D1KL, TempCo="200 ppm/C", Tolerance_%=1%, Value2=0.05W, Value_Code=1k00, ValueDisplayed=1.00k
R9 R62 R63 R167: library part CMP-0026578-2, "RES, 84.5 k, 1%, 0.063 W, AEC-Q200 Grade 0, 0402", Manufacturer=Vishay-Dale, Power_W=63mW, Supplier Part Number 1=541-84.5KLCT-ND, TempCo="100 ppm/C", Tolerance_%=1%, Value2=0.063W, Value_Code=84k5, ValueDisplayed=84.5k
R10 R64 R77 R78 R160 R172: library part CMP-0026440-2, "RES, 523, 1%, 0.063 W, AEC-Q200 Grade 0, 0402", Manufacturer=Vishay-Dale, Power_W=63mW, Supplier Part Number 1=541-523LCT-ND, TempCo="100 ppm/C", Tolerance_%=1%, Value2=0.063W, Value_Code=523R, ValueDisplayed=523
R11: library part CMP-0026339-2, "RES, 3.83 k, 1%, 0.063 W, AEC-Q200 Grade 0, 0402", Manufacturer=Vishay-Dale, Power_W=63mW, Supplier Part Number 1=541-3.83KLCT-ND, TempCo="100 ppm/C", Tolerance_%=1%, Value2=0.063W, Value_Code=3k83, ValueDisplayed=3.83k
R12 R16 R24 R37 R40 R41 R42 R43 R44 R45 R46 R48 R49 R51 R54 R60 R61 R94 R106 R108 R110 R111 R132 R147 R161 R162 R173 R174 R186 R187 R189 R190 R191 R192 R193: library part CMP-0027008-1, "RES, 0, 5%, 0.05 W, 0201", Manufacturer=Vishay-Dale, Power_W=50mW, Supplier Part Number 1=72M6743, TempCo=ppm/C, Tolerance_%=5%, Value2=0.05W, Value_Code=0000, ValueDisplayed=0
R13 R20: library part CMP-0022822-4, "RES, 162 k, 1%, 0.1 W, 0603", Manufacturer=Yageo, Power_W=100mW, Supplier Part Number 1=311-162KHRCT-ND, TempCo="100 ppm/C", Tolerance_%=1%, Value2=0.1W, Value_Code=162k
R15: library part CMP-0027811-1, "RES, 61.9 k, 1%, 0.05 W, 0201", Manufacturer="Yageo America", Power_W=50mW, Supplier Part Number 1=YAG2751CT-ND, TempCo="200 ppm/C", Tolerance_%=1%, Value2=0.05W, Value_Code=61k9, ValueDisplayed=61.9k
R17: library part CMP-0027638-1, "RES, 37.4 k, 1%, 0.05 W, 0201", Manufacturer="Yageo America", Power_W=50mW, Supplier Part Number 1=YAG2631CT-ND, TempCo="200 ppm/C", Tolerance_%=1%, Value2=0.05W, Value_Code=37k4, ValueDisplayed=37.4k
R18 R98: library part CMP-0027901-1, "RES, 86.6 k, 1%, 0.05 W, 0201", Manufacturer="Yageo America", Power_W=50mW, Supplier Part Number 1=YAG2825CT-ND, TempCo="200 ppm/C", Tolerance_%=1%, Value2=0.05W, Value_Code=86k6, ValueDisplayed=86.6k
R19: library part CMP-0025976-3, "RES, 11.3 k, 1%, 0.063 W, AEC-Q200 Grade 0, 0402", Manufacturer=Vishay-Dale, Power_W=63mW, Supplier Part Number 1=541-11.3KLCT-ND, TempCo="100 ppm/C", Tolerance_%=1%, Value2=0.063W, Value_Code=11k3, ValueDisplayed=11.3k
R25 R26 R27 R32 R33 R38 R39 R72 R73 R74 R85 R87 R122 R123 R124 R125 R127 R131 R138 R139 R140 R141 R142 R143 R144 R148 R149 R168 R180 R184: library part CMP-0028071-1, "RES SMD 10K OHM 1% 1/20W 0201", Manufacturer="Samsung Electro-Mechanics", PartNumber=RC0603F103CS, Power_W=50mW, Supplier Part Number 1=1276-3670-1-ND, TempCo="200 ppm/C", Tolerance_%=1%, Value2=0.05W, Value_Code=10k0, ValueDisplayed=10.0k
R28 R66 R116: library part CMP-0021986-1, "RES, 0.02, 1%, 0.5 W, 0805", Manufacturer=Vishay-Dale, Power_W=500mW, Supplier Part Number 1=WSLPB-.02CT-ND, TempCo="75 ppm/C", Tolerance_%=1%, Value2=0.5W, Value_Code=R020, ValueDisplayed=0.02
R30 R31 R70 R71 R145 R146: library part CMP-0027946-1, "RES, 10.0, 1%, 0.05 W, 0201", Manufacturer="Yageo America", Power_W=50mW, Supplier Part Number 1=603-RC0201FR-7D10RL, TempCo="350 ppm/C", Tolerance_%=1%, Value2=0.05W, Value_Code=10R0, ValueDisplayed=10.0
R47 R50 R53 R55 R56 R57 R58 R59: library part CMP-0027413-1, "RES, 18.0, 1%, 0.05 W, 0201", Manufacturer="Yageo America", Power_W=50mW, Supplier Part Number 1=YAG2459CT-ND, TempCo="200 ppm/C", Tolerance_%=1%, Value2=0.05W, Value_Code=18R0, ValueDisplayed=18.0
R68: library part CMP-0027485-1, "RES, 21.5 k, 1%, 0.05 W, 0201", Manufacturer="Yageo America", Power_W=50mW, Supplier Part Number 1=YAG2505CT-ND, TempCo="200 ppm/C", Tolerance_%=1%, Value2=0.05W, Value_Code=21k5, ValueDisplayed=21.5k
R75 R86 R88 R181: library part CMP-0027640-1, "RES, 383 k, 1%, 0.05 W, 0201", Manufacturer="Yageo America", Power_W=50mW, Supplier Part Number 1=YAG2633CT-ND, TempCo="200 ppm/C", Tolerance_%=1%, Value2=0.05W, Value_Code=383k
R76 R89 R90 R171: library part CMP-0026845-3, "RES SMD 330 OHM 1% 1/10W 0402", Manufacturer="Panasonic Electronic Components", PartNumber=ERJ-2RKF3300X, Power_W=63mW, TempCo="200 ppm/C", Tolerance_%=1%, Value1=5%, Value2=0.063W, Value_Code=160R, ValueDisplayed=330
R83: library part CMP-0027335-2, "RES, 12.4 k, 1%, 0.05 W, 0201", Manufacturer="Yageo America", Power_W=50mW, Supplier Part Number 1=311-12.4KMCT-ND, TempCo="200 ppm/C", Tolerance_%=1%, Value2=0.05W, Value_Code=12k4, ValueDisplayed=12.4k
R84: library part CMP-0027996-1, "RES, 2.49 k, 1%, 0.05 W, 0201", Manufacturer="Yageo America", Power_W=50mW, Supplier Part Number 1=603-RC0201FR-7D2K49L, TempCo="200 ppm/C", Tolerance_%=1%, Value2=0.05W, Value_Code=2k49, ValueDisplayed=2.49k
R92 R100 R103: library part CMP-0027945-1, "RES, 10.0 k, 1%, 0.05 W, 0201", Manufacturer="Yageo America", Power_W=50mW, Supplier Part Number 1=603-RC0201FR-7D10KL, TempCo="200 ppm/C", Tolerance_%=1%, Value2=0.05W, Value_Code=10k0, ValueDisplayed=10.0k
R93 R104 R105 R113 R150 R152 R195: library part CMP-0025885-5, "RES, 0, 5%, 0.1 W, 0603", Manufacturer=Yageo, Power_W=100mW, Supplier Part Number 1=311-0.0GRCT-ND, TempCo="200 ppm/C", Tolerance_%=5%, Value2=0.1W, Value_Code=0000, ValueDisplayed=0
R95: library part CMP-0028099-1, "RES, 301 k, 1%, 0.05 W, 0201", Manufacturer="Yageo America", Power_W=50mW, Supplier Part Number 1=603-RC0201FS-7D301KL, TempCo="200 ppm/C", Tolerance_%=1%, Value2=0.05W, Value_Code=301k
R96: library part CMP-0027720-1, "RES, 475 k, 1%, 0.05 W, 0201", Manufacturer="Yageo America", Power_W=50mW, Supplier Part Number 1=YAG2690CT-ND, TempCo="200 ppm/C", Tolerance_%=1%, Value2=0.05W, Value_Code=475k
R97: library part CMP-0027636-1, "RES, 374 k, 1%, 0.05 W, 0201", Manufacturer="Yageo America", Power_W=50mW, Supplier Part Number 1=YAG2629CT-ND, TempCo="200 ppm/C", Tolerance_%=1%, Value2=0.05W, Value_Code=374k
R99: library part CMP-0027450-1, "RES, 1.80 k, 1%, 0.05 W, 0201", Manufacturer="Yageo America", Power_W=50mW, Supplier Part Number 1=YAG2492CT-ND, TempCo="200 ppm/C", Tolerance_%=1%, Value2=0.05W, Value_Code=1k80, ValueDisplayed=1.80k
R101: library part CMP-0027606-1, "RES, 32.4 k, 1%, 0.05 W, 0201", Manufacturer="Yageo America", Power_W=50mW, Supplier Part Number 1=YAG2601CT-ND, TempCo="200 ppm/C", Tolerance_%=1%, Value2=0.05W, Value_Code=32k4, ValueDisplayed=32.4k
R102: library part CMP-0027696-1, "RES, 42.2 k, 1%, 0.05 W, 0201", Manufacturer="Yageo America", Power_W=50mW, Supplier Part Number 1=YAG2666CT-ND, TempCo="200 ppm/C", Tolerance_%=1%, Value2=0.05W, Value_Code=42k2, ValueDisplayed=42.2k
R107: library part CMP-0026828-1, "RES, 110 k, 5%, 0.063 W, 0402", Manufacturer=Vishay-Dale, Power_W=63mW, Supplier Part Number 1=541-110KJCT-ND, TempCo="200 ppm/C", Tolerance_%=5%, Value2=0.063W, Value_Code=110k
R109: library part CMP-0027529-1, "RES, 26.1 k, 1%, 0.05 W, 0201", Manufacturer="Yageo America", Power_W=50mW, Supplier Part Number 1=YAG2544CT-ND, TempCo="200 ppm/C", Tolerance_%=1%, Value2=0.05W, Value_Code=26k1, ValueDisplayed=26.1k
R112: library part CMP-0026725-1, "RES, 1.00 k, 1%, 0.0625 W, 0402", Manufacturer="Yageo America", Power_W=62.5mW, Supplier Part Number 1=311-1.00KLRCT-ND, TempCo="100 ppm/C", Tolerance_%=1%, Value2=0.0625W, Value_Code=1k00, ValueDisplayed=1.00k
R118 R133: library part CMP-0026394-2, "RES, 475, 1%, 0.063 W, AEC-Q200 Grade 0, 0402", Manufacturer=Vishay-Dale, Power_W=63mW, Supplier Part Number 1=541-475LCT-ND, TempCo="100 ppm/C", Tolerance_%=1%, Value2=0.063W, Value_Code=475R, ValueDisplayed=475
R121: library part CMP-0027626-1, "RES, 35.7 k, 1%, 0.05 W, 0201", Manufacturer="Yageo America", Power_W=50mW, Supplier Part Number 1=YAG2619CT-ND, TempCo="200 ppm/C", Tolerance_%=1%, Value2=0.05W, Value_Code=35k7, ValueDisplayed=35.7k
R126: library part CMP-0028031-1, "RES, 4.70 k, 1%, 0.05 W, 0201", Manufacturer="Yageo America", Power_W=50mW, Supplier Part Number 1=603-RC0201FR-7D4K7L, TempCo="200 ppm/C", Tolerance_%=1%, Value2=0.05W, Value_Code=4k70, ValueDisplayed=4.70k
R128: library part CMP-0027332-1, "RES, 127 k, 1%, 0.05 W, 0201", Manufacturer="Yageo America", Power_W=50mW, Supplier Part Number 1=311-127KMCT-ND, TempCo="200 ppm/C", Tolerance_%=1%, Value2=0.05W, Value_Code=127k
R129: library part CMP-0026448-2, "RES, 549, 1%, 0.063 W, AEC-Q200 Grade 0, 0402", Manufacturer=Vishay-Dale, Power_W=63mW, Supplier Part Number 1=541-549LCT-ND, TempCo="100 ppm/C", Tolerance_%=1%, Value2=0.063W, Value_Code=549R, ValueDisplayed=549
R130: library part CMP-0027943-1, "RES, 100 k, 1%, 0.05 W, 0201", Manufacturer="Yageo America", Power_W=50mW, Supplier Part Number 1=603-RC0201FR-7D100KL, TempCo="200 ppm/C", Tolerance_%=1%, Value2=0.05W, Value_Code=100k
R134 R135: library part CMP-0026824-3, "RES, 100, 5%, 0.063 W, AEC-Q200 Grade 0, 0402", Manufacturer=Vishay-Dale, Power_W=63mW, Supplier Part Number 1=541-100JCT-ND, TempCo="200 ppm/C", Tolerance_%=5%, Value2=0.063W, Value_Code=100R, ValueDisplayed=100
R136: library part CMP-0027790-1, "RES, 5.23 k, 1%, 0.05 W, 0201", Manufacturer="Yageo America", Power_W=50mW, Supplier Part Number 1=YAG2742CT-ND, TempCo="200 ppm/C", Tolerance_%=1%, Value2=0.05W, Value_Code=5k23, ValueDisplayed=5.23k
R137: library part CMP-0027594-1, "RES, 30.1 k, 1%, 0.05 W, 0201", Manufacturer="Yageo America", Power_W=50mW, Supplier Part Number 1=YAG2590CT-ND, TempCo="200 ppm/C", Tolerance_%=1%, Value2=0.05W, Value_Code=30k1, ValueDisplayed=30.1k
R151 R164: library part CMP-0026071-3, "RES, 1.00 k, 1%, 0.063 W, AEC-Q200 Grade 0, 0402", Manufacturer=Vishay-Dale, Power_W=63mW, Supplier Part Number 1=541-1.00KLCT-ND, TempCo="100 ppm/C", Tolerance_%=1%, Value2=0.063W, Value_Code=1k00, ValueDisplayed=1.00k
R165: library part CMP-0026051-3, "RES, 17.8 k, 1%, 0.063 W, AEC-Q200 Grade 0, 0402", Manufacturer=Vishay-Dale, Power_W=63mW, Supplier Part Number 1=541-17.8KLCT-ND, TempCo="100 ppm/C", Tolerance_%=1%, Value2=0.063W, Value_Code=17k8, ValueDisplayed=17.8k
R166: library part CMP-0026237-2, "RES, 2.49 k, 1%, 0.063 W, AEC-Q200 Grade 0, 0402", Manufacturer=Vishay-Dale, Power_W=63mW, Supplier Part Number 1=541-2.49KLCT-ND, TempCo="100 ppm/C", Tolerance_%=1%, Value2=0.063W, Value_Code=2k49, ValueDisplayed=2.49k
R169: library part CMP-0026321-2, "RES, 383 k, 1%, 0.063 W, AEC-Q200 Grade 0, 0402", Manufacturer=Vishay-Dale, Power_W=63mW, Supplier Part Number 1=541-383KLCT-ND, TempCo="100 ppm/C", Tolerance_%=1%, Value2=0.063W, Value_Code=383k
R170: library part CMP-0025993-3, "RES, 12.7 k, 1%, 0.063 W, AEC-Q200 Grade 0, 0402", Manufacturer=Vishay-Dale, Power_W=63mW, Supplier Part Number 1=541-12.7KLCT-ND, TempCo="100 ppm/C", Tolerance_%=1%, Value2=0.063W, Value_Code=12k7, ValueDisplayed=12.7k
R176: library part CMP-0026241-2, "RES, 2.74 k, 1%, 0.063 W, AEC-Q200 Grade 0, 0402", Manufacturer=Vishay-Dale, Power_W=63mW, Supplier Part Number 1=541-2.74KLCT-ND, TempCo="100 ppm/C", Tolerance_%=1%, Value2=0.063W, Value_Code=2k74, ValueDisplayed=2.74k
R177: library part CMP-0027878-1, "RES, 7.50 k, 1%, 0.05 W, 0201", Manufacturer="Yageo America", Power_W=50mW, Supplier Part Number 1=RC0201FR-077K5L-ND, TempCo="200 ppm/C", Tolerance_%=1%, Value2=0.05W, Value_Code=7k50, ValueDisplayed=7.50k
R179: library part CMP-0026232-2, "RES, 2.21 k, 1%, 0.063 W, AEC-Q200 Grade 0, 0402", Manufacturer=Vishay-Dale, Power_W=63mW, Supplier Part Number 1=541-2.21KLCT-ND, TempCo="100 ppm/C", Tolerance_%=1%, Value2=0.063W, Value_Code=2k21, ValueDisplayed=2.21k
R182: library part CMP-0026414-2, "RES, 4.99 k, 1%, 0.063 W, AEC-Q200 Grade 0, 0402", Manufacturer=Vishay-Dale, Power_W=63mW, Supplier Part Number 1=541-4.99KLCT-ND, TempCo="100 ppm/C", Tolerance_%=1%, Value2=0.063W, Value_Code=4k99, ValueDisplayed=4.99k
R183: library part CMP-0026841-3, "RES, 150, 5%, 0.063 W, AEC-Q200 Grade 0, 0402", Manufacturer="Panasonic Electronic Components", PartNumber=ERJ-2RKF2200X, Power_W=63mW, TempCo="200 ppm/C", Tolerance_%=1%, Value2=0.063W, Value_Code=220R, ValueDisplayed=220
R185: library part CMP-0025990-3, "RES, 12.0 k, 1%, 0.063 W, AEC-Q200 Grade 0, 0402", Manufacturer=Vishay-Dale, Power_W=63mW, Supplier Part Number 1=541-12.0KLCT-ND, TempCo="100 ppm/C", Tolerance_%=1%, Value2=0.063W, Value_Code=12k0, ValueDisplayed=12.0k
R194: library part CMP-0091603-1, "0 Ohms Jumper 0.5W, 1/2W Chip Resistor 0805 (2012 Metric) Automotive AEC-Q200 Metal Foil", Digikey Part Number=HCJ0805ZT0R00CT-ND, Manufacturer=Stackpole, Operating Temperature Range="-55°C to +155°C", Power=500mW
S1: library part CMP-0002302-1, "Switch, SPST, Off-Mom, 0.05 A, 12 VDC, SMD", CurrentRating_mA=50A, Manufacturer="Wurth Elektronik", Supplier Part Number 1=732-10143-1-ND
SCL SDA: library part CMP-0078143-2, "TEST POINT.  No entry in BOM.", Manufacturer=N/A
U1: library part CMP-0092925-1, "2.2-MHz Wide VIN 85-V Boost/Sepic/Flyback Converter with Dual Random Spread Spectrum, 1.5A, WQFN16", Manufacturer="Texas Instruments", Max Supply Voltage=60V, Min Supply Voltage=1.5V, Nominal Supply Current=670uA, Operating Temperature Range="-40°C to +150°C", Output Voltage=1.5-83V, Switching Frequency=100-2200kHz
U2: library part CMP-0091224-1, "10-Bit and 8-Bit, Voltage-Output Digital-to-Analog Converters With Nonvolatile Memory and PMBus™ Compatible I 2C Interface in Tiny 2 × 2 WSON", Digikey Part Number=296-DAC53401DSGRCT-ND, Manufacturer="Texas Instruments", Max Supply Voltage=5.5V, Min Supply Voltage=1.71V, Mouser Part Number=595-DAC53401DSGR, Nominal Supply Current=0.5mA, Operating Temperature Range="-40°C to +125°C"
U3 U12 U23: library part CMP-0065450-1, "28-V, Bi-Directional, Zero-Drift, Low-/High-Side, I2C Out Current/Power Monitor w/ Alert in WCSP, YFF0012AKAD (DSBGA-12)", Alternate Manufacturer="Texas Instruments", Alternate PartNumber=INA231AIYFFT
U5: library part CMP-0075866-2, "Programmable 4-PLL VCXO Clock Synthesizer with 2.5V or 3.3V LVCMOS Outputs, PW0024A (TSSOP-24)", Alternate Manufacturer="Texas Instruments", Alternate PartNumber=CDCE949PW, Operating Temperature Range="-40 to 85 C", Rating=Catalog
U6 U7 U8: library part CMP-0051217-4, "Single 3-Input Positive-AND Gate, DRY0006A (USON-6)", F @ Nom Voltage(Max)(Mhz)=150, Generic Part Number=SN74LVC1G11, ICC @ Nom Voltage(Max)(mA)=0.01, Manufacturer="Texas Instruments", Operating Temperature Range="-40 to 125 C", Operating Temperature Range(C)="-40 to 125,-40 to 85", Rating=Catalog, tpd @ Nom Voltage(Max)(ns)=20,7.8,6.2,4.6, Voltage(Nom)(V)=1.8,2.5,3.3,5
U9: library part CMP-0071684-1, "Power Sequencer, 6-pin SOT-23, 1000 Reel", Manufacturer="Texas Instruments", PackageTopMarking=F20A*XTT, PowerWise=N
U11 U14 U25: library part CMP-0073970-3, "2.95V to 6V Input, 2A Synchronous Step-Down SWIFT(TM) Converter, RTE0016F (WQFN-16)", Alternate Manufacturer="Texas Instruments", Alternate PartNumber=TPS54218RTET
U13: library part CMP-0073970-1, "2.95V to 6V Input, 2A Synchronous Step-Down SWIFT(TM) Converter, RTE0016F (WQFN-16)", Alternate Manufacturer="Texas Instruments", Alternate PartNumber=TPS54218RTET
U15: library part CMP-0013943-2, "20 Vout Fully Integration Synchronous Boost Converter with 8 A Switch Current, RNW0013A (VQFN-HR-13)", Alternate Manufacturer="Texas Instruments", Alternate PartNumber=TPS61178RNWT
U16: library part CMP-0013435-7, "Dual, 150mA, Wide-Vin, Positive and Negative Low-Dropout (LDO) Voltage Regulator, DSC0010J (WSON-10)", Alternate Manufacturer="Texas Instruments", Alternate PartNumber=TPS7A3901DSCT, Operating Temperature Range="-40 to 125 C", Rating=Catalog
U17: library part CMP-0065261-6, "36-V 1-A Step-Down DC-DC Nano Module, SIL0010A (uSIP-10)", Alternate Manufacturer="Texas Instruments", Alternate PartNumber=LMZM23601SILT, PartNumber=pt
U18: library part CMP-0085942-4, "BQ25790, PREYBG0056 (DSBGA-56)", Alternate Manufacturer="Texas Instruments"
U19: library part CMP-0861022-1, "23 V, 6 A, 24.5 mΩ Reverse Current Blocking eFuse with Input Reverse Polarity Protection, RPW0010A (VQFN-HR-10)", Alternate Manufacturer="Texas Instruments"
U20: library part CMP-0051481-2, "Single Positive-Edge-Triggered D-Type Flip-Flop With Clear and Preset, DQE0008A, LARGE T&R", F @ Nom Voltage(Max)(Mhz)=150, Generic Part Number=SN74LVC1G74, ICC @ Nom Voltage(Max)(mA)=0.01, Manufacturer="Texas Instruments", Operating Temperature Range(C)="-40 to 125", Rating=Catalog, tpd @ Nom Voltage(Max)(ns)=13.4,7.1,5.9,4.1, Voltage(Nom)(V)=1.8,2.5,3.3,5
U21: library part CMP-0074236-1, "Single Channel Push Button Controller with Configurable Delay and Reset Pulse, DRY0006A (USON-6)", Alternate Manufacturer="Texas Instruments", Alternate PartNumber=TPS3422EGDRYT
U26: library part CMP-0096730-1, "2-A, Ultra-low Noise, Ultra-high PSRR, RF Voltage Regulator", Dropout Voltage=215mV, Manufacturer="Texas Instruments", Max Supply Voltage=5.7V, Min Supply Voltage=1.7V, Nominal Supply Current=15-49mA, Operating Temperature Range="-40°C to +125°C", Output Voltage=0.4-5.5V
U27: library part CMP-0860372-1, "2.95V to 6V Input, 3A Synchronous Step-Down SWIFT™ Converter, RTE0016F (WQFN-16)", Alternate Manufacturer="Texas Instruments", Alternate PartNumber=TPS54318RTET, Operating Temperature Range="-40 to 150 C", Rating=Catalog
U28: library part CMP-0036360-4, "Single-Output LDO, 3A, Adj (0.8V to 3.3V), Fast Transient Response, Programmable Soft Start, RGW0020A (VQFN-20)", Manufacturer="Texas Instruments", Operating Temperature Range="-40 to 125 C", Power Good=TRUE, Rating=Catalog
ZZ1: library part AssemblyNoteLabel
ZZ2 ZZ3 ZZ4: library part AssemblyNote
